// Mitsubishi GX Works2 project: FX2N PLC与海利普变频器通讯   PLC: FX2N/FX2NC

PROGRAM MAIN
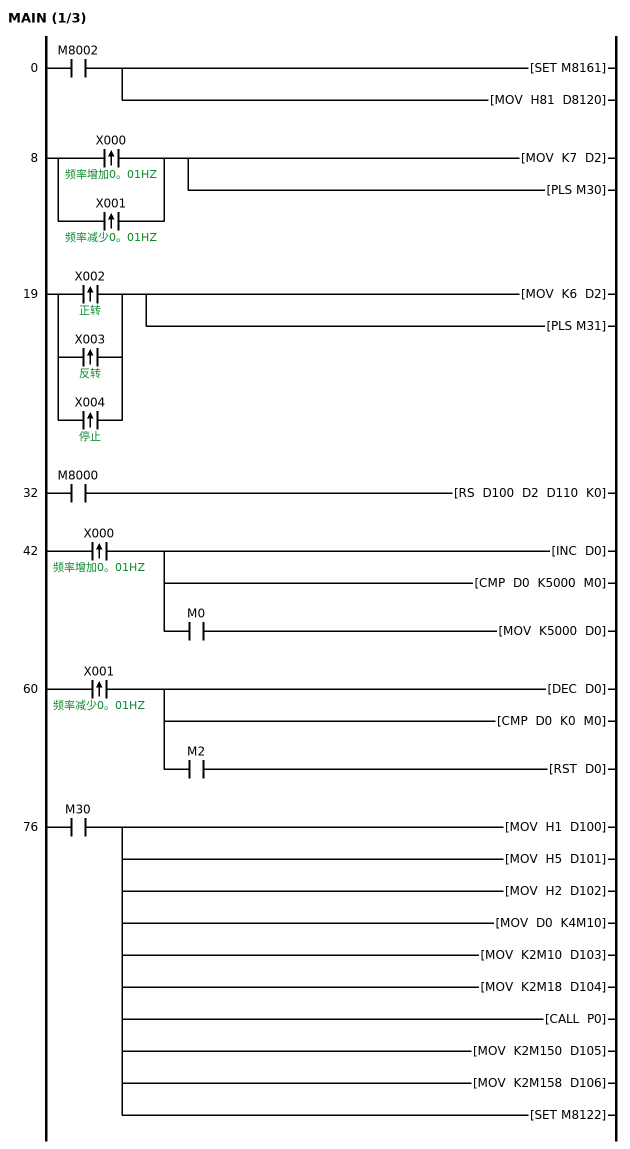
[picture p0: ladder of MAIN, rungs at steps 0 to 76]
0     LD      M8002
      SET     M8161
      MOV     H81 D8120
8     LDP     X000  ; 频率增加0。01HZ
      ORP     X001  ; 频率减少0。01HZ
      MOV     K7 D2
      PLS     M30
19    LDP     X002  ; 正转
      ORP     X003  ; 反转
      ORP     X004  ; 停止
      MOV     K6 D2
      PLS     M31
32    LD      M8000
      RS      D100 D2 D110 K0
42    LDP     X000  ; 频率增加0。01HZ
      INC     D0
      CMP     D0 K5000 M0
      AND     M0
      MOV     K5000 D0
60    LDP     X001  ; 频率减少0。01HZ
      DEC     D0
      CMP     D0 K0 M0
      AND     M2
      RST     D0
76    LD      M30
      MOV     H1 D100
      MOV     H5 D101
      MOV     H2 D102
      MOV     D0 K4M10
      MOV     K2M10 D103
      MOV     K2M18 D104
      CALL    P0
      MOV     K2M150 D105
      MOV     K2M158 D106
      SET     M8122
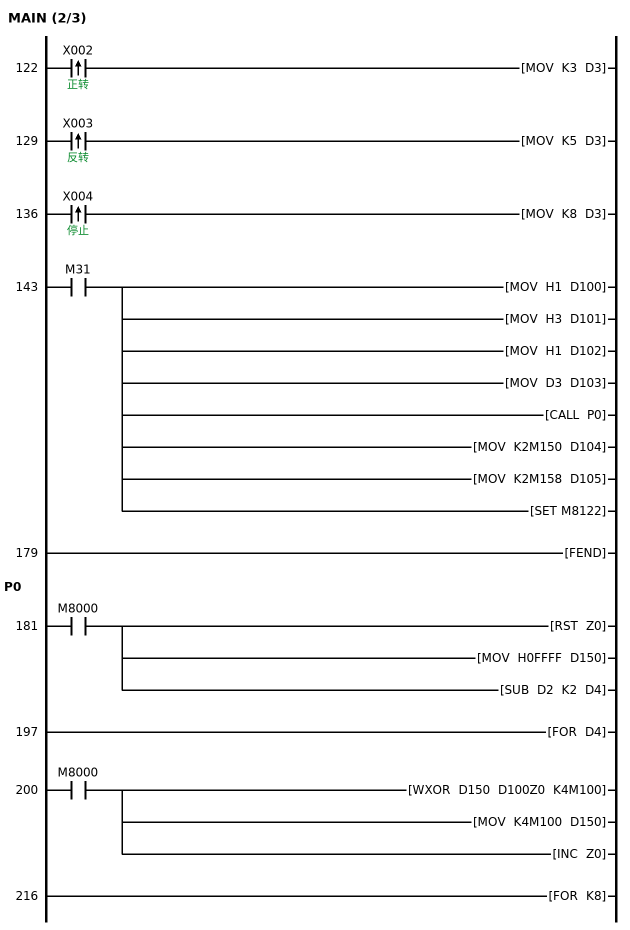
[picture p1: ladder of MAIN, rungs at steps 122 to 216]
122   LDP     X002  ; 正转
      MOV     K3 D3
129   LDP     X003  ; 反转
      MOV     K5 D3
136   LDP     X004  ; 停止
      MOV     K8 D3
143   LD      M31
      MOV     H1 D100
      MOV     H3 D101
      MOV     H1 D102
      MOV     D3 D103
      CALL    P0
      MOV     K2M150 D104
      MOV     K2M158 D105
      SET     M8122
179   FEND
      P0
181   LD      M8000
      RST     Z0
      MOV     H0FFFF D150
      SUB     D2 K2 D4
197   FOR     D4
200   LD      M8000
      WXOR    D150 D100Z0 K4M100
      MOV     K4M100 D150
      INC     Z0
216   FOR     K8
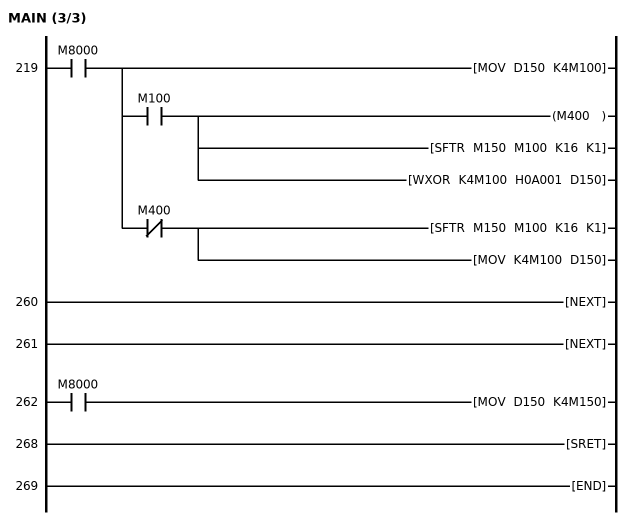
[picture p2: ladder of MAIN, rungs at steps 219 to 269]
219   LD      M8000
      MOV     D150 K4M100
      MPS
      AND     M100
      OUT     M400
      SFTR    M150 M100 K16 K1
      WXOR    K4M100 H0A001 D150
      MPP
      ANI     M400
      SFTR    M150 M100 K16 K1
      MOV     K4M100 D150
260   NEXT
261   NEXT
262   LD      M8000
      MOV     D150 K4M150
268   SRET
269   END
END_PROGRAM
